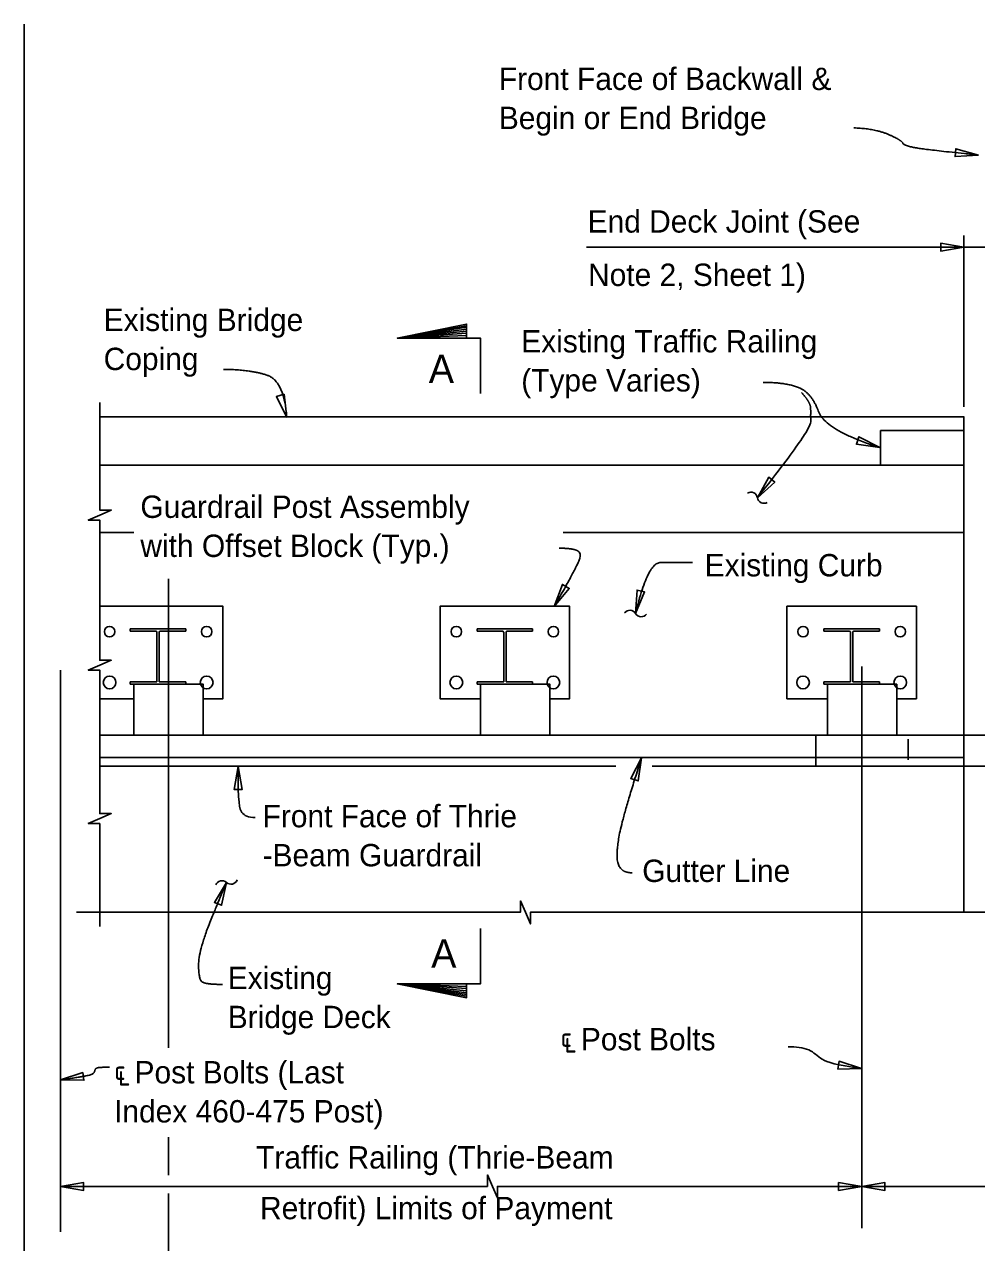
# Model space of a CAD drawing. Extents: x 21526.6 to 21598.7, y 56118.9 to 56155.9.
# Drawn here: x 21545.72 to 21554.3, y 56142.28 to 56153.26 of the extents above; entities that cross this region are included whole.
import ezdxf

# ---------------------------------------------------------------- set-up
doc = ezdxf.new("R2010")
doc.units = 0
for name, color, linetype in [('AdhocPoint_dp', 7, 'Continuous'), ('Border', 7, 'Continuous'), ('Patterning', 7, 'Continuous'), ('PlotBorder_dp', 7, 'Continuous'), ('SheetBorder_dp', 7, 'Continuous'), ('TextMisc', 7, 'Continuous')]:
    doc.layers.add(name, color=color, linetype=linetype)

msp = doc.modelspace()

# ---------------------------------------------------------------- linework, layer by layer
at = {"layer": 'AdhocPoint_dp'}
for p, q in [((21554.182, 56149.72), (21546.396, 56149.72)), ((21554.182, 56149.722), (21554.182, 56145.254)), ((21553.432, 56149.595), (21554.182, 56149.595)), ((21546.396, 56149.282), (21554.182, 56149.282)), ((21546.396, 56148.678), (21546.702, 56148.678)), ((21550.571, 56148.678), (21554.182, 56148.678)), ((21546.395, 56146.648), (21554.182, 56146.648))]:
    msp.add_line(p, q, dxfattribs=at)
msp.add_lwpolyline([(21553.432, 56149.595), (21553.432, 56149.282)], dxfattribs=at)
at = {"layer": 'Border'}
msp.add_open_spline([(21550.536, 56148.535), (21550.639, 56148.535), (21550.736, 56148.502), (21550.706, 56148.382), (21550.491, 56148.01)], degree=2, dxfattribs=at)
at = {"layer": 'Patterning'}
for p, q in [((21547.015, 56144.034), (21547.015, 56148.26)), ((21546.042, 56147.435), (21546.042, 56142.373)), ((21547.015, 56142.884), (21547.015, 56143.228)), ((21547.015, 56136.022), (21547.015, 56142.721))]:
    msp.add_line(p, q, dxfattribs=at)
for points in [[(21546.703, 56147.309), (21546.703, 56146.851), (21547.328, 56146.851), (21547.328, 56147.309)], [(21549.828, 56147.309), (21549.828, 56146.851), (21550.453, 56146.851), (21550.453, 56147.309)], [(21552.953, 56147.309), (21552.953, 56146.851), (21553.578, 56146.851), (21553.578, 56147.309)]]:
    msp.add_lwpolyline(points, close=True, dxfattribs=at)
at = {"layer": 'PlotBorder_dp'}
for p, q in [((21545.716, 56153.256), (21545.716, 56127.317)), ((21554.182, 56149.808), (21554.182, 56151.352)), ((21554.69, 56151.248), (21550.781, 56151.248)), ((21549.076, 56150.429), (21549.701, 56150.539)), ((21549.701, 56150.526), (21549.076, 56150.429)), ((21549.076, 56150.429), (21549.701, 56150.509)), ((21549.701, 56150.491), (21549.076, 56150.429)), ((21549.076, 56150.429), (21549.701, 56150.473)), ((21549.701, 56150.453), (21549.076, 56150.429)), ((21553.263, 56142.407), (21553.263, 56147.47)), ((21549.701, 56144.586), (21549.076, 56144.609)), ((21549.076, 56144.609), (21549.701, 56144.566)), ((21549.701, 56144.547), (21549.076, 56144.609)), ((21549.076, 56144.609), (21549.701, 56144.529)), ((21549.701, 56144.512), (21549.076, 56144.609)), ((21549.076, 56144.609), (21549.701, 56144.499))]:
    msp.add_line(p, q, dxfattribs=at)
for points in [[(21554.314, 56152.078), (21554.11, 56152.134), (21554.103, 56152.064)], [(21554.182, 56151.248), (21553.974, 56151.283), (21553.974, 56151.212)], [(21548.081, 56149.712), (21548.056, 56149.922), (21547.988, 56149.902)], [(21553.424, 56149.441), (21553.237, 56149.539), (21553.215, 56149.472)], [(21552.322, 56148.989), (21552.479, 56149.131), (21552.424, 56149.175)], [(21550.491, 56148.01), (21550.626, 56148.173), (21550.565, 56148.208)], [(21551.224, 56147.946), (21551.306, 56148.141), (21551.238, 56148.157)], [(21551.279, 56146.647), (21551.181, 56146.46), (21551.248, 56146.438)], [(21547.642, 56146.569), (21547.607, 56146.36), (21547.678, 56146.36)], [(21547.539, 56145.523), (21547.429, 56145.343), (21547.494, 56145.317)], [(21553.26, 56143.847), (21553.048, 56143.841), (21553.058, 56143.911)], [(21546.042, 56143.743), (21546.253, 56143.74), (21546.242, 56143.809)], [(21546.042, 56142.784), (21546.25, 56142.748), (21546.25, 56142.819)], [(21553.263, 56142.784), (21553.054, 56142.819), (21553.054, 56142.748)], [(21553.263, 56142.784), (21553.471, 56142.819), (21553.471, 56142.748)]]:
    msp.add_lwpolyline(points, close=True, dxfattribs=at)
for points in [[(21549.826, 56149.929), (21549.826, 56150.429), (21549.076, 56150.429), (21549.701, 56150.554), (21549.701, 56150.429)], [(21546.396, 56148.32), (21546.396, 56148.789), (21546.292, 56148.789), (21546.396, 56148.834), (21546.499, 56148.879), (21546.396, 56148.879), (21546.396, 56149.848)], [(21546.396, 56146.573), (21546.396, 56147.436), (21546.292, 56147.436), (21546.396, 56147.481), (21546.499, 56147.526), (21546.396, 56147.526), (21546.396, 56148.32)], [(21546.396, 56145.126), (21546.396, 56146.054), (21546.292, 56146.054), (21546.396, 56146.099), (21546.499, 56146.144), (21546.396, 56146.144), (21546.396, 56147.017)], [(21546.187, 56145.254), (21550.187, 56145.254), (21550.187, 56145.357), (21550.232, 56145.254), (21550.277, 56145.15), (21550.277, 56145.254), (21554.19, 56145.254)], [(21554.182, 56145.254), (21556.177, 56145.254), (21556.177, 56145.357), (21556.222, 56145.254), (21556.267, 56145.15), (21556.267, 56145.254), (21558.132, 56145.254)], [(21549.826, 56145.109), (21549.826, 56144.609), (21549.076, 56144.609), (21549.701, 56144.484), (21549.701, 56144.609)], [(21546.042, 56142.784), (21549.889, 56142.784), (21549.889, 56142.887), (21549.934, 56142.784), (21549.979, 56142.68), (21549.979, 56142.784), (21562.023, 56142.784)]]:
    msp.add_lwpolyline(points, dxfattribs=at)
for centre, start, end in [((21552.263, 56148.981), 8.6098, 120.3371), ((21552.381, 56148.999), 188.6098, 300.3371), ((21551.173, 56147.916), 30.7941, 142.5214), ((21551.276, 56147.977), 210.7941, 322.5214), ((21547.497, 56145.479), 47.1839, 158.9112), ((21547.578, 56145.567), 227.1839, 338.9112)]:
    msp.add_arc(centre, 0.0596, start, end, dxfattribs=at)
for points, degree in [([(21553.192, 56152.323), (21553.377, 56152.316), (21553.614, 56152.217), (21553.647, 56152.158), (21553.918, 56152.118), (21554.314, 56152.078)], 2), ([(21547.51, 56150.146), (21547.749, 56150.146), (21548.058, 56150.042), (21548.081, 56149.712)], 2), ([(21552.719, 56149.939), (21552.802, 56149.846), (21552.802, 56149.749), (21552.802, 56149.595), (21552.322, 56148.989)], 2), ([(21552.374, 56150.029), (21552.585, 56150.029), (21552.813, 56149.932), (21552.933, 56149.6), (21553.424, 56149.441)], 2), ([(21551.737, 56148.405), (21551.562, 56148.405), (21551.333, 56148.405), (21551.224, 56147.946)], 2), ([(21551.194, 56145.61), (21551.098, 56145.61), (21551.042, 56145.755), (21551.111, 56146.134), (21551.279, 56146.647)], 2), ([(21547.797, 56146.107), (21547.731, 56146.11), (21547.667, 56146.137), (21547.642, 56146.231), (21547.642, 56146.569)], 3), ([(21547.501, 56144.604), (21547.349, 56144.604), (21547.286, 56144.65), (21547.286, 56144.908), (21547.494, 56145.424), (21547.539, 56145.523)], 2), ([(21552.6, 56144.043), (21552.664, 56144.041), (21552.808, 56144.028), (21552.884, 56143.922), (21553.025, 56143.88), (21553.26, 56143.847)], 3), ([(21546.484, 56143.858), (21546.418, 56143.858), (21546.354, 56143.851), (21546.345, 56143.794), (21546.219, 56143.77), (21546.042, 56143.743)], 2)]:
    msp.add_open_spline(points, degree=degree, dxfattribs=at)
at = {"layer": 'SheetBorder_dp'}
for p, q in [((21552.848, 56146.57), (21552.848, 56146.851)), ((21552.848, 56146.851), (21566.396, 56146.851)), ((21553.682, 56146.628), (21553.682, 56146.813)), ((21552.848, 56146.57), (21566.234, 56146.57))]:
    msp.add_line(p, q, dxfattribs=at)
at = {"layer": 'TextMisc'}
for p, q in [((21547.171, 56147.809), (21546.671, 56147.809)), ((21546.671, 56147.809), (21546.671, 56147.788)), ((21546.9, 56147.788), (21546.671, 56147.788)), ((21546.911, 56147.778), (21546.911, 56147.33)), ((21546.932, 56147.778), (21546.932, 56147.33)), ((21547.171, 56147.788), (21546.942, 56147.788)), ((21547.171, 56147.809), (21547.171, 56147.788)), ((21550.296, 56147.809), (21549.796, 56147.809)), ((21549.796, 56147.809), (21549.796, 56147.788)), ((21550.025, 56147.788), (21549.796, 56147.788)), ((21550.036, 56147.778), (21550.036, 56147.33)), ((21550.057, 56147.778), (21550.057, 56147.33)), ((21550.296, 56147.788), (21550.067, 56147.788)), ((21550.296, 56147.809), (21550.296, 56147.788)), ((21553.421, 56147.809), (21552.921, 56147.809)), ((21552.921, 56147.809), (21552.921, 56147.788)), ((21553.15, 56147.788), (21552.921, 56147.788)), ((21553.161, 56147.778), (21553.161, 56147.33)), ((21553.182, 56147.778), (21553.182, 56147.33)), ((21553.421, 56147.788), (21553.192, 56147.788)), ((21553.421, 56147.809), (21553.421, 56147.788)), ((21546.911, 56147.33), (21546.671, 56147.33)), ((21546.671, 56147.309), (21546.671, 56147.33)), ((21547.171, 56147.309), (21546.671, 56147.309)), ((21547.171, 56147.33), (21546.932, 56147.33)), ((21547.171, 56147.309), (21547.171, 56147.33)), ((21550.036, 56147.33), (21549.796, 56147.33)), ((21549.796, 56147.309), (21549.796, 56147.33)), ((21550.296, 56147.309), (21549.796, 56147.309)), ((21550.296, 56147.33), (21550.057, 56147.33)), ((21550.296, 56147.309), (21550.296, 56147.33)), ((21553.161, 56147.33), (21552.921, 56147.33)), ((21552.921, 56147.309), (21552.921, 56147.33)), ((21553.421, 56147.309), (21552.921, 56147.309)), ((21553.421, 56147.33), (21553.182, 56147.33)), ((21553.421, 56147.309), (21553.421, 56147.33)), ((21546.395, 56146.851), (21552.848, 56146.851)), ((21546.395, 56146.57), (21551.046, 56146.57)), ((21551.375, 56146.57), (21552.848, 56146.57))]:
    msp.add_line(p, q, dxfattribs=at)
for points in [[(21546.396, 56148.012), (21547.505, 56148.012), (21547.505, 56147.179), (21547.328, 56147.179)], [(21549.828, 56147.179), (21549.463, 56147.179), (21549.463, 56148.012), (21550.63, 56148.012), (21550.63, 56147.179), (21550.453, 56147.179)], [(21552.953, 56147.179), (21552.588, 56147.179), (21552.588, 56148.012), (21553.755, 56148.012), (21553.755, 56147.179), (21553.578, 56147.179)], [(21546.703, 56147.179), (21546.396, 56147.179)]]:
    msp.add_lwpolyline(points, dxfattribs=at)
for centre, radius in [((21546.484, 56147.783), 0.0469), ((21547.359, 56147.783), 0.0469), ((21549.609, 56147.783), 0.0469), ((21550.484, 56147.783), 0.0469), ((21552.734, 56147.783), 0.0469), ((21553.609, 56147.783), 0.0469), ((21546.484, 56147.325), 0.0573), ((21547.359, 56147.325), 0.0573), ((21549.609, 56147.325), 0.0573), ((21550.484, 56147.325), 0.0573), ((21552.734, 56147.325), 0.0573), ((21553.609, 56147.325), 0.0573)]:
    msp.add_circle(centre, radius, dxfattribs=at)
for centre, start, end in [((21546.9, 56147.778), 0, 90), ((21546.942, 56147.778), 90, 180), ((21550.025, 56147.778), 0, 90), ((21550.067, 56147.778), 90, 180), ((21553.15, 56147.778), 0, 90), ((21553.192, 56147.778), 90, 180)]:
    msp.add_arc(centre, 0.0104, start, end, dxfattribs=at)

# ---------------------------------------------------------------- texts
at = {"layer": 'Border'}
for s, height, p in [('End Deck Joint (See', 0.2016, (21550.792, 56151.379)), ('Note 2, Sheet 1)', 0.2016, (21550.796, 56150.898)), ('A', 0.256, (21549.36, 56150.023)), ('Existing Curb', 0.2016, (21551.847, 56148.281)), ('Gutter Line', 0.2016, (21551.284, 56145.527)), ('A', 0.256, (21549.382, 56144.754)), ('℄ Post Bolts', 0.2016, (21550.547, 56144.01))]:
    msp.add_text(s, height=height, dxfattribs=at).set_placement(p)
at = {"layer": 'PlotBorder_dp'}
for s, p in [('Front Face of Backwall &', (21549.992, 56152.664)), ('Begin or End Bridge', (21549.992, 56152.312)), ('Existing Bridge ', (21546.431, 56150.492)), ('Existing Traffic Railing', (21550.194, 56150.299)), ('Coping ', (21546.431, 56150.14)), ('(Type Varies)', (21550.194, 56149.947)), ('Guardrail Post Assembly ', (21546.762, 56148.808)), ('with Offset Block (Typ.)', (21546.762, 56148.456)), ('Front Face of Thrie', (21547.863, 56146.02)), ('-Beam Guardrail', (21547.863, 56145.668)), ('Existing ', (21547.549, 56144.562)), ('Bridge Deck', (21547.549, 56144.21)), ('℄ Post Bolts (Last', (21546.525, 56143.712)), ('Index 460-475 Post)', (21546.525, 56143.36)), ('Traffic Railing (Thrie-Beam ', (21547.805, 56142.945)), ('Retrofit) Limits of Payment', (21547.84, 56142.488))]:
    msp.add_text(s, height=0.2016, dxfattribs=at).set_placement(p)

doc.saveas('drawing.dxf')
